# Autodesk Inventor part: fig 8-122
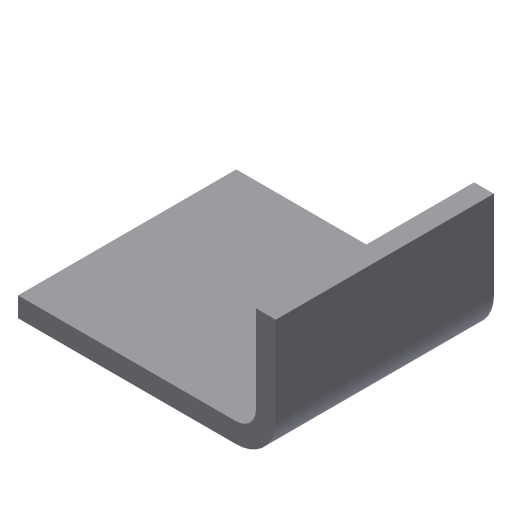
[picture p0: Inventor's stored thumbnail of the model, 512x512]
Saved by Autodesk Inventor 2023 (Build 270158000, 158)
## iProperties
Created: 2009-09
Part Number: fig 8-122
Document SubType Name: Modeling
Designer: Sham
Density: 1 g/cm^3
Material: Generic
Appearance: Default
Author: Sham
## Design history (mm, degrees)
sketch "Sketch1"
  geometry: L1 (-33.976, 22)-(0, 22); L2 (0, 22)-(0, 0); L3 (0, 0)-(-33.976, 0); L4 (-33.976, 0)-(-33.976, 22)
  constraints: 8 end point, 2 parallel, 1 horizontal, 1 perpendicular
extrude "Extrusion1" new body sketch "Sketch1" distance "d0" = 2; taper "d1" = 0 deg
sketch "Sketch2"
  geometry: L1 (-12, 22)-(-12, 0)
  constraints: 2 end point
feature "Bend Part1" sketch "Sketch2" dims "d5" = 90 deg, "d6" = 2
body "Solid1"
